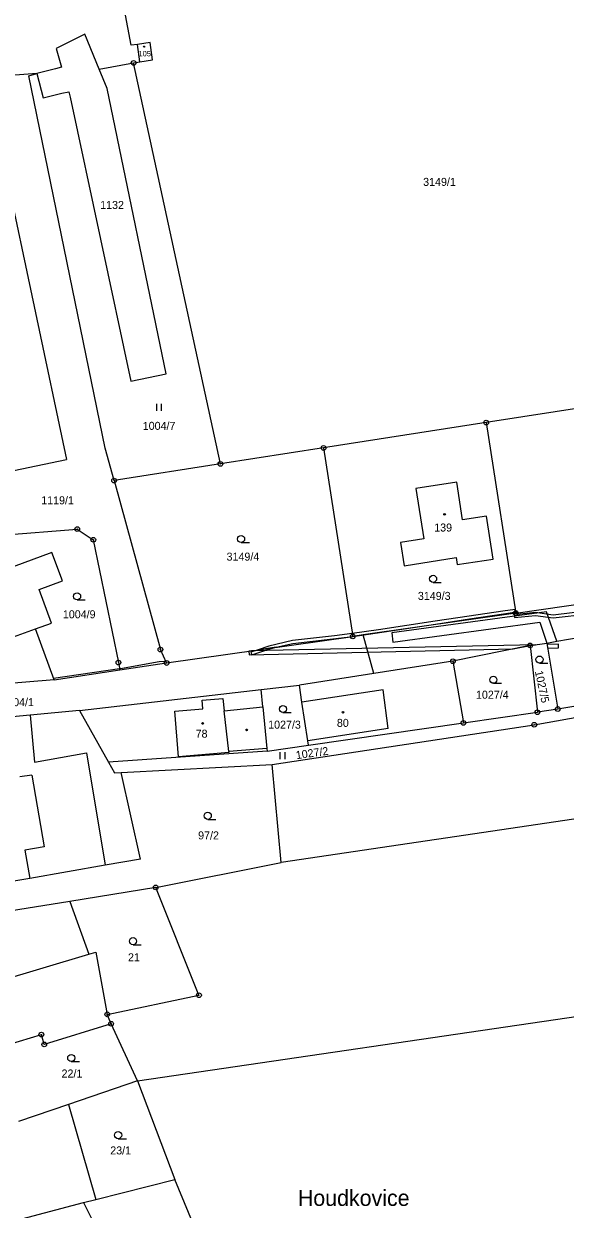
# Model space of a CAD drawing. Extents: x -618848 to -615803, y -1044450 to -1042254.
# Drawn here: x -616880.4 to -616765.3, y -1043145.8 to -1042894.1 of the extents above; entities that cross this region are included whole.
import ezdxf
from ezdxf.enums import TextEntityAlignment as Align

# ---------------------------------------------------------------- set-up
doc = ezdxf.new("R2010")
doc.units = 0
doc.header["$LTSCALE"] = 0.68
for name, color, linetype, lineweight in [('1', 7, 'Continuous', 25), ('13', 7, 'Continuous', 13), ('3', 7, 'Continuous', 25), ('4', 7, 'Continuous', 13), ('5', 7, 'Continuous', 25), ('7', 7, 'Continuous', 13), ('8', 7, 'Continuous', 25)]:
    doc.layers.add(name, color=color, linetype=linetype, lineweight=lineweight)
doc.layers.add('2', color=7, linetype='Continuous')

msp = doc.modelspace()

# ---------------------------------------------------------------- linework, layer by layer
at = {"layer": '1'}
for p, q in [((-616857.58, -1042898.69), (-616858.98, -1042891.17)), ((-616867.42, -1042896.33), (-616873.53, -1042899.35)), ((-616864.35, -1042903.74), (-616867.42, -1042896.33)), ((-616873.53, -1042899.35), (-616872.36, -1042903.36)), ((-616856.23, -1042898.55), (-616857.58, -1042898.69)), ((-616853.56, -1042898.13), (-616856.23, -1042898.55)), ((-616855.7, -1042902.19), (-616856.23, -1042898.55)), ((-616853.04, -1042901.81), (-616853.56, -1042898.13)), ((-616864.35, -1042903.74), (-616857.05, -1042902.43)), ((-616857.05, -1042902.43), (-616855.7, -1042902.19)), ((-616838.59, -1042987.59), (-616857.05, -1042902.43)), ((-616855.7, -1042902.19), (-616853.04, -1042901.81)), ((-616877.6, -1042904.7), (-616888.48, -1042905.51)), ((-616879.34, -1042905.15), (-616877.6, -1042904.7)), ((-616863.07, -1042984.27), (-616879.34, -1042905.15)), ((-616873.63, -1042903.69), (-616877.6, -1042904.7)), ((-616877.6, -1042904.7), (-616876.28, -1042909.84)), ((-616872.36, -1042903.36), (-616873.63, -1042903.69)), ((-616862.64, -1042907.89), (-616864.35, -1042903.74)), ((-616850.14, -1042968.48), (-616862.64, -1042907.89)), ((-616876.28, -1042909.84), (-616872.32, -1042908.83)), ((-616872.32, -1042908.83), (-616870.85, -1042908.55)), ((-616870.85, -1042908.55), (-616870.51, -1042909.73)), ((-616870.51, -1042909.73), (-616857.67, -1042970.04)), ((-616884.48, -1042924.34), (-616871.3, -1042986.62)), ((-616857.67, -1042970.04), (-616850.14, -1042968.48)), ((-616747.51, -1042973.43), (-616782.1, -1042978.8)), ((-616782.1, -1042978.8), (-616816.67, -1042984.18)), ((-616782.1, -1042978.8), (-616775.81, -1043019.26)), ((-616861.2, -1042991.11), (-616863.07, -1042984.27)), ((-616816.67, -1042984.18), (-616838.59, -1042987.59)), ((-616816.67, -1042984.18), (-616810.46, -1043024.2)), ((-616882.51, -1042988.99), (-616871.3, -1042986.62)), ((-616838.59, -1042987.59), (-616861.2, -1042991.11)), ((-616861.2, -1042991.11), (-616851.36, -1043027)), ((-616788.37, -1042991.45), (-616797.03, -1042992.78)), ((-616797.03, -1042992.78), (-616795.37, -1043003.46)), ((-616787.12, -1042999.46), (-616788.37, -1042991.45)), ((-616782.04, -1042998.67), (-616787.12, -1042999.46)), ((-616780.63, -1043007.79), (-616782.04, -1042998.67)), ((-616885.1, -1043002.71), (-616869.02, -1043001.41)), ((-616869.02, -1043001.41), (-616865.61, -1043003.68)), ((-616795.37, -1043003.46), (-616800.32, -1043004.24)), ((-616865.61, -1043003.68), (-616860.29, -1043029.75)), ((-616800.32, -1043004.24), (-616799.55, -1043009.19)), ((-616874.4, -1043006.38), (-616882.66, -1043009.42)), ((-616872.17, -1043012.4), (-616874.4, -1043006.38)), ((-616799.55, -1043009.19), (-616788.49, -1043007.48)), ((-616788.49, -1043007.48), (-616788.25, -1043008.95)), ((-616788.25, -1043008.95), (-616780.63, -1043007.79)), ((-616877.14, -1043014.24), (-616872.17, -1043012.4)), ((-616874.49, -1043021.36), (-616877.14, -1043014.24)), ((-616775.81, -1043019.26), (-616744.11, -1043014.73)), ((-616775.81, -1043019.26), (-616808.22, -1043023.88)), ((-616767.05, -1043025.24), (-616743.22, -1043020.94)), ((-616877.88, -1043022.59), (-616874.49, -1043021.36)), ((-616873.95, -1043033.42), (-616877.88, -1043022.59)), ((-616850.03, -1043029.85), (-616810.46, -1043024.2)), ((-616808.22, -1043023.88), (-616810.46, -1043024.2)), ((-616805.95, -1043032.08), (-616808.22, -1043023.88)), ((-616772.77, -1043026.13), (-616789.17, -1043029.49)), ((-616772.77, -1043026.13), (-616769.21, -1043025.63)), ((-616772.77, -1043026.13), (-616771.21, -1043040.31)), ((-616769.21, -1043025.63), (-616767.05, -1043025.24)), ((-616769.21, -1043025.63), (-616766.88, -1043039.62)), ((-616850.03, -1043029.85), (-616851.36, -1043027)), ((-616860.29, -1043029.75), (-616859.97, -1043031.33)), ((-616859.97, -1043031.33), (-616850.03, -1043029.85)), ((-616789.17, -1043029.49), (-616805.95, -1043032.08)), ((-616789.17, -1043029.49), (-616786.94, -1043042.57)), ((-616873.95, -1043033.42), (-616893.84, -1043035.01)), ((-616873.95, -1043033.42), (-616859.97, -1043031.33)), ((-616805.95, -1043032.08), (-616821.81, -1043034.53)), ((-616868.53, -1043039.91), (-616829.91, -1043035.46)), ((-616829.91, -1043035.46), (-616821.81, -1043034.53)), ((-616829.55, -1043039.19), (-616829.91, -1043035.46)), ((-616821.26, -1043038.17), (-616821.81, -1043034.53)), ((-616741.71, -1043035.58), (-616766.88, -1043039.62)), ((-616820.03, -1043046.36), (-616821.26, -1043038.17)), ((-616771.88, -1043042.97), (-616741.39, -1043037.56)), ((-616879.04, -1043040.92), (-616885.84, -1043041.57)), ((-616868.53, -1043039.91), (-616879.04, -1043040.92)), ((-616868.53, -1043039.91), (-616862.36, -1043050.94)), ((-616829.55, -1043039.19), (-616828.71, -1043047.97)), ((-616786.94, -1043042.57), (-616771.21, -1043040.31)), ((-616766.88, -1043039.62), (-616771.21, -1043040.31)), ((-616819.89, -1043047.31), (-616786.94, -1043042.57)), ((-616828.65, -1043048.57), (-616862.36, -1043050.94)), ((-616828.71, -1043047.97), (-616828.65, -1043048.57)), ((-616828.65, -1043048.57), (-616819.89, -1043047.31)), ((-616819.89, -1043047.31), (-616820.03, -1043046.36)), ((-616862.36, -1043050.94), (-616861.1, -1043053.19)), ((-616678.35, -1043050.51), (-616825.7, -1043072.18)), ((-616861.1, -1043053.19), (-616859.67, -1043053.11)), ((-616859.67, -1043053.11), (-616827.57, -1043051.4)), ((-616855.58, -1043071.48), (-616859.67, -1043053.11)), ((-616855.58, -1043071.48), (-616863.06, -1043072.78)), ((-616863.06, -1043072.78), (-616879.12, -1043075.58)), ((-616852.35, -1043077.5), (-616825.7, -1043072.18)), ((-616879.12, -1043075.58), (-616885.52, -1043076.7)), ((-616852.35, -1043077.5), (-616870.62, -1043080.46)), ((-616843.15, -1043100.39), (-616852.35, -1043077.5)), ((-616870.62, -1043080.46), (-616883.43, -1043082.53)), ((-616870.62, -1043080.46), (-616866.54, -1043091.67)), ((-616866.54, -1043091.67), (-616865.1, -1043091.24)), ((-616865.1, -1043091.24), (-616862.65, -1043104.45)), ((-616856.2, -1043118.59), (-616665.88, -1043090.61)), ((-616898.17, -1043101.09), (-616866.54, -1043091.67)), ((-616862.65, -1043104.45), (-616843.15, -1043100.39)), ((-616861.82, -1043106.44), (-616876.03, -1043110.85)), ((-616861.82, -1043106.44), (-616862.65, -1043104.45)), ((-616856.2, -1043118.59), (-616861.82, -1043106.44)), ((-616886.19, -1043111.61), (-616876.66, -1043108.75)), ((-616876.03, -1043110.85), (-616876.66, -1043108.75)), ((-616856.2, -1043118.59), (-616870.89, -1043123.58)), ((-616856.2, -1043118.59), (-616848.28, -1043139.55)), ((-616870.89, -1043123.58), (-616881.5, -1043127.19)), ((-616870.89, -1043123.58), (-616865.06, -1043143.76)), ((-616865.06, -1043143.76), (-616848.28, -1043139.55)), ((-616840.92, -1043157.18), (-616848.28, -1043139.55)), ((-616881.88, -1043148.18), (-616867.68, -1043144.42)), ((-616867.68, -1043144.42), (-616865.06, -1043143.76)), ((-616867.68, -1043144.42), (-616858.92, -1043161.88))]:
    msp.add_line(p, q, dxfattribs=at)
msp.add_lwpolyline([(-616825.7, -1043072.18), (-616827.57, -1043051.4), (-616771.88, -1043042.97)], dxfattribs=at)
at = {"layer": '13'}
for points in [[(-616760.36, -1043018.79), (-616767.84, -1043019.67), (-616771.58, -1043019.15), (-616775.51, -1043019.56), (-616775.51, -1043019.22), (-616775.81, -1043019.26), (-616776.11, -1043019.3), (-616776.11, -1043020.22), (-616771.6, -1043019.75), (-616767.84, -1043020.27), (-616760.28, -1043019.39), (-616748.46, -1043017.21), (-616739.23, -1043015.66), (-616729.82, -1043014.17), (-616720.16, -1043012.17), (-616719.72, -1043010.35), (-616720.38, -1043010.47), (-616720.66, -1043011.65), (-616729.93, -1043013.58), (-616739.33, -1043015.06), (-616748.54, -1043016.62)], [(-616810.56, -1043023.58), (-616810.46, -1043024.2), (-616792.84, -1043021.6), (-616785.62, -1043020.48), (-616778.45, -1043019.41), (-616776.05, -1043019.04), (-616776.02, -1043019.29), (-616775.81, -1043019.26), (-616775.93, -1043018.51), (-616778.53, -1043018.81), (-616785.72, -1043019.88), (-616792.94, -1043021), (-616804.97, -1043022.81)], [(-616775.74, -1043018.99), (-616775.93, -1043018.51), (-616775.81, -1043019.26), (-616775.7, -1043019.24)], [(-616801.95, -1043025.42), (-616770.69, -1043021.18), (-616769.21, -1043025.63), (-616767.05, -1043025.24), (-616769.25, -1043018.96), (-616802.17, -1043023.43)], [(-616776.11, -1043019.3), (-616775.81, -1043019.26), (-616775.84, -1043019.07), (-616776.12, -1043019.08)], [(-616775.51, -1043019.05), (-616775.84, -1043019.07), (-616775.81, -1043019.26), (-616775.51, -1043019.22)], [(-616823.27, -1043025.09), (-616828.28, -1043026.27), (-616830.78, -1043027.1), (-616826.73, -1043026.52), (-616823.17, -1043025.69), (-616810.46, -1043024.2), (-616810.56, -1043023.58), (-616814.36, -1043024.1)], [(-616832.51, -1043028.09), (-616776.38, -1043026.87), (-616772.77, -1043026.13), (-616771.6, -1043025.97), (-616832, -1043027.28), (-616832.52, -1043027.35)], [(-616766.74, -1043025.86), (-616769.16, -1043025.91), (-616769.03, -1043026.71), (-616766.75, -1043026.66)], [(-616826.73, -1043026.52), (-616830.78, -1043027.1), (-616832.1, -1043027.54), (-616831.91, -1043028.11), (-616828.12, -1043026.85)], [(-616860.02, -1043031.11), (-616874.05, -1043033.14), (-616873.95, -1043033.42), (-616859.97, -1043031.33)], [(-616859.97, -1043031.33), (-616850.03, -1043029.85), (-616850.17, -1043029.54), (-616851.61, -1043029.61), (-616859.83, -1043031.08), (-616860.02, -1043031.11)]]:
    msp.add_lwpolyline(points, close=True, dxfattribs=at)
at = {"layer": '3'}
for p, q in [((-616852.111, -1042976.32), (-616852.111, -1042974.82)), ((-616851.11, -1042976.32), (-616851.11, -1042974.82)), ((-616834.193, -1043004.28), (-616832.443, -1043004.28)), ((-616793.383, -1043012.73), (-616791.633, -1043012.73)), ((-616869.063, -1043016.45), (-616867.313, -1043016.45)), ((-616770.763, -1043029.87), (-616769.013, -1043029.87)), ((-616780.563, -1043034.16), (-616778.813, -1043034.16)), ((-616825.303, -1043040.37), (-616823.553, -1043040.37)), ((-616825.861, -1043050.27), (-616825.861, -1043048.77)), ((-616824.86, -1043050.27), (-616824.86, -1043048.77)), ((-616841.283, -1043063.05), (-616839.533, -1043063.05)), ((-616857.173, -1043089.66), (-616855.423, -1043089.66)), ((-616870.303, -1043114.47), (-616868.553, -1043114.47)), ((-616860.333, -1043130.85), (-616858.583, -1043130.85))]:
    msp.add_line(p, q, dxfattribs=at)
for centre in [(-616834.1929, -1043003.5298), (-616793.3829, -1043011.9798), (-616869.0629, -1043015.6998), (-616770.7629, -1043029.1198), (-616780.5629, -1043033.4098), (-616825.3029, -1043039.6198), (-616841.2829, -1043062.2998), (-616857.1729, -1043088.9098), (-616870.3029, -1043113.7198), (-616860.3329, -1043130.0998)]:
    msp.add_circle(centre, 0.75, dxfattribs=at)
at = {"layer": '4'}
for p, q in [((-616885.77, -1043025.46), (-616877.88, -1043022.59)), ((-616803.99, -1043035.58), (-616821.26, -1043038.17)), ((-616802.95, -1043043.79), (-616803.99, -1043035.58)), ((-616842.5, -1043037.77), (-616838.06, -1043037.37)), ((-616842.33, -1043039.61), (-616842.5, -1043037.77)), ((-616838.06, -1043037.37), (-616837.79, -1043039.99)), ((-616879.04, -1043040.92), (-616878.09, -1043050.92)), ((-616848.29, -1043040.09), (-616842.33, -1043039.61)), ((-616847.52, -1043049.75), (-616848.29, -1043040.09)), ((-616837.79, -1043039.99), (-616829.55, -1043039.19)), ((-616836.79, -1043048.62), (-616837.79, -1043039.99)), ((-616802.95, -1043043.79), (-616820.03, -1043046.36)), ((-616828.71, -1043047.97), (-616836.79, -1043048.62)), ((-616836.79, -1043048.62), (-616836.77, -1043048.88)), ((-616878.09, -1043050.92), (-616867.08, -1043048.95)), ((-616867.08, -1043048.95), (-616863.06, -1043072.78)), ((-616836.77, -1043048.88), (-616847.52, -1043049.75)), ((-616878.67, -1043053.68), (-616881.26, -1043054.01)), ((-616878.67, -1043053.68), (-616876.03, -1043068.85)), ((-616876.03, -1043068.85), (-616880.17, -1043069.57)), ((-616880.17, -1043069.57), (-616879.12, -1043075.58))]:
    msp.add_line(p, q, dxfattribs=at)
at = {"layer": '5'}
for centre, radius in [((-616854.8246, -1042898.9794), 0.1172), ((-616790.9468, -1042998.2992), 0.175), ((-616812.5368, -1043040.2992), 0.175), ((-616842.3668, -1043042.6892), 0.175), ((-616833.0168, -1043044.0492), 0.175)]:
    msp.add_circle(centre, radius, dxfattribs=at)
at = {"layer": '8'}
for centre, radius in [((-616857.05, -1042902.4299), 0.5), ((-616857.05, -1042902.4299), 0.0303), ((-616782.1, -1042978.7999), 0.5), ((-616782.1, -1042978.7999), 0.0303), ((-616816.67, -1042984.1799), 0.5), ((-616816.67, -1042984.1799), 0.0303), ((-616838.59, -1042987.5899), 0.5), ((-616838.59, -1042987.5899), 0.0303), ((-616861.2, -1042991.1099), 0.5), ((-616861.2, -1042991.1099), 0.0303), ((-616869.02, -1043001.4099), 0.5), ((-616869.02, -1043001.4099), 0.0303), ((-616865.61, -1043003.6799), 0.5), ((-616865.61, -1043003.6799), 0.0303), ((-616775.81, -1043019.2599), 0.5), ((-616775.81, -1043019.2599), 0.0303), ((-616810.46, -1043024.1999), 0.5), ((-616810.46, -1043024.1999), 0.0303), ((-616772.77, -1043026.1299), 0.5), ((-616772.77, -1043026.1299), 0.0303), ((-616851.36, -1043026.9999), 0.5), ((-616851.36, -1043026.9999), 0.0303), ((-616860.29, -1043029.7499), 0.5), ((-616860.29, -1043029.7499), 0.0303), ((-616850.03, -1043029.8499), 0.5), ((-616850.03, -1043029.8499), 0.0303), ((-616789.17, -1043029.4899), 0.5), ((-616789.17, -1043029.4899), 0.0303), ((-616771.21, -1043040.3099), 0.5), ((-616771.21, -1043040.3099), 0.0303), ((-616766.88, -1043039.6199), 0.5), ((-616766.88, -1043039.6199), 0.0303), ((-616786.94, -1043042.5699), 0.5), ((-616786.94, -1043042.5699), 0.0303), ((-616771.88, -1043042.9699), 0.5), ((-616771.88, -1043042.9699), 0.0303), ((-616852.35, -1043077.4999), 0.5), ((-616852.35, -1043077.4999), 0.0303), ((-616843.15, -1043100.3899), 0.5), ((-616843.15, -1043100.3899), 0.0303), ((-616862.65, -1043104.4499), 0.5), ((-616862.65, -1043104.4499), 0.0303), ((-616861.82, -1043106.4399), 0.5), ((-616861.82, -1043106.4399), 0.0303), ((-616876.66, -1043108.7499), 0.5), ((-616876.66, -1043108.7499), 0.0303), ((-616876.03, -1043110.8499), 0.5), ((-616876.03, -1043110.8499), 0.0303)]:
    msp.add_circle(centre, radius, dxfattribs=at)

# ---------------------------------------------------------------- texts
at = {"layer": '2'}
for s, height, p in [('105', 1.14, (-616854.68, -1042901.035)), ('3149/1', 1.7, (-616792.02, -1042928.545)), ('1132', 1.7, (-616861.63, -1042933.445)), ('1004/7', 1.7, (-616851.63, -1042980.345)), ('1119/1', 1.7, (-616873.21, -1042996.155)), ('139', 1.7, (-616791.249, -1043001.935)), ('3149/4', 1.7, (-616833.81, -1043008.115)), ('3149/3', 1.7, (-616793.14, -1043016.455)), ('1004/9', 1.7, (-616868.61, -1043020.355)), ('1027/4', 1.7, (-616780.79, -1043037.435)), ('1104/1', 1.7, (-616881.71, -1043039.015)), ('1027/3', 1.7, (-616824.97, -1043043.795)), ('80', 1.7, (-616812.569, -1043043.415)), ('78', 1.7, (-616842.599, -1043045.715)), ('97/2', 1.7, (-616841.119, -1043067.305)), ('21', 1.7, (-616856.979, -1043093.185)), ('22/1', 1.7, (-616870.149, -1043117.865)), ('23/1', 1.7, (-616859.799, -1043134.195))]:
    msp.add_text(s, height=height, dxfattribs=at).set_placement(p, align=Align.CENTER)
for s, rotation, p in [('1027/5', 282, (-616771.0361, -1043035.0478)), ('1027/2', 8, (-616818.9898, -1043049.8021))]:
    msp.add_text(s, height=1.7, rotation=rotation, dxfattribs=at).set_placement(p, align=Align.CENTER)
at = {"layer": '7'}
msp.add_text('Houdkovice', height=3.4, dxfattribs=at).set_placement((-616822.14, -1043145.13))

doc.saveas('drawing.dxf')
